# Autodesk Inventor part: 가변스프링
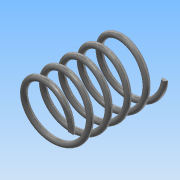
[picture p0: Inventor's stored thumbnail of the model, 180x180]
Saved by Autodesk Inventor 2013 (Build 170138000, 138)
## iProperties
Created: 2017-01
Part Number: 가변스프링
Material: 스테인리스강
Document SubType Name: Modeling
Designer: Administrator
Mass: 63.1926 g
Surface Area: 78.9695 cm^2
Volume: 7.82087 cm^3
Density: 8.08 g/cm^3
Author: Administrator
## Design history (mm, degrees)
sketch "스케치1"
  geometry: L1 (0, 0)-(20, 0); L2 (20, 0)-(20, 67.25); L3 (20, 67.25)-(0, 67.25); L4 (0, 67.25)-(0, 0); C1 r 2 at (20, 0)
  constraints: 8 end point, 2 parallel, 1 centre point, 1 coincident, 1 horizontal, 1 perpendicular
  dimensions: "d0" = 4 diameter of C1; "d2" = 67.25 distance of L3.end L1.start (derived); "d3" = 40 diameter of L2 L4
feature "코일1" sketch "스케치1" pitch "d4" = 10; turns "d6" = 5; dims "d5" = 67.25 (= d2), "d7" = 0, angle "d8" = 90 deg, angle "d9" = 90 deg, "d10" = 0, "d11" = 0
sketch "스케치2"
  geometry: L1 (0, 26.801)-(67.25, 26.801); L2 (67.25, 26.801)-(67.25, -26.801); L3 (67.25, -26.801)-(0, -26.801); L4 (0, -26.801)-(0, 26.801); 4 further points
  constraints: 8 end point, 2 coincident, 2 midpoint, 2 parallel, 1 horizontal, 1 perpendicular
  dimensions: "d12" = 53.60174 distance of L1.end L2.end
extrude "돌출1" sketch "스케치2" stored distance "d14" = 0; taper "d15" = 0 deg
node "솔리드1"
